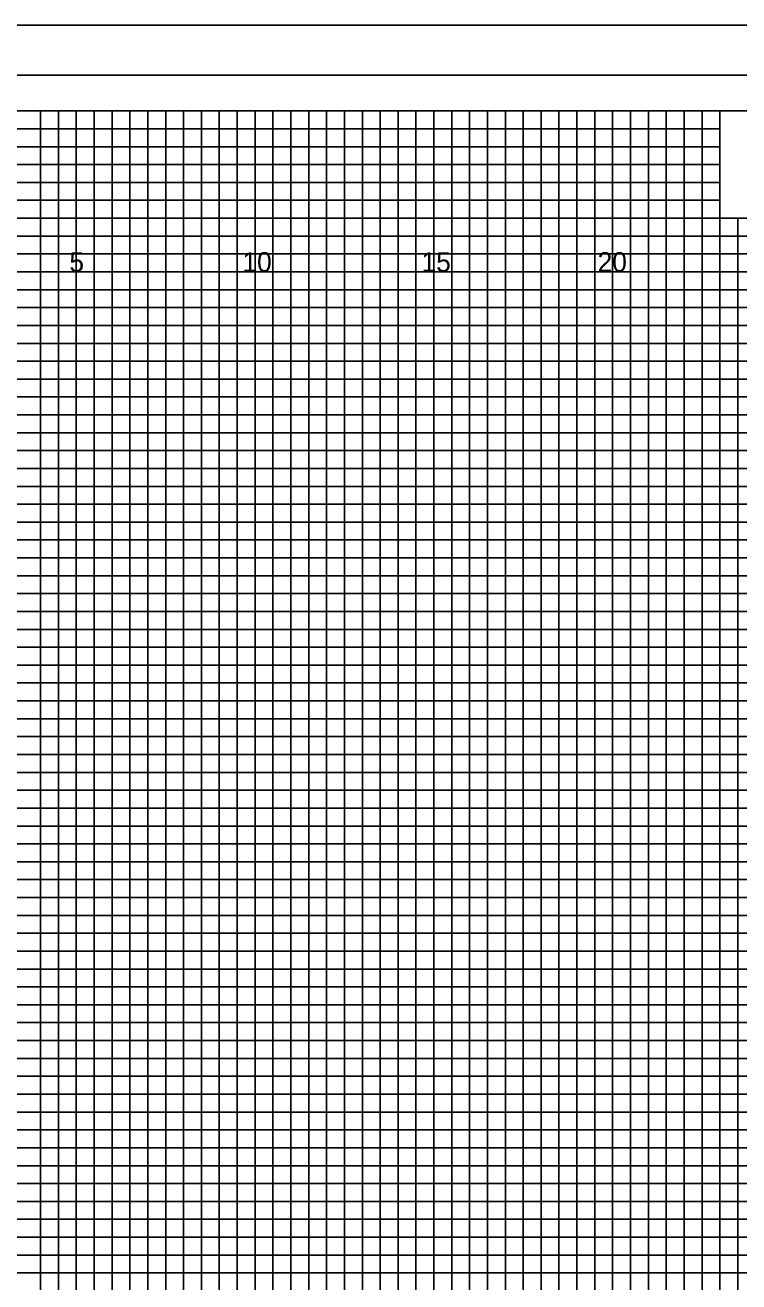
# Model space of a CAD drawing. Extents: x -4 to 103, y -2 to 67.
# Drawn here: x 54.82 to 74.78, y 32.25 to 67.4 of the extents above; entities that cross this region are included whole.
import ezdxf

# ---------------------------------------------------------------- set-up
doc = ezdxf.new("R2010")
doc.units = 0
for name, color, linetype in [('Old_Level_10', 7, 'Continuous'), ('Old_Level_16', 7, 'Continuous'), ('Old_Level_3', 7, 'Continuous'), ('Old_Level_4', 7, 'Continuous'), ('Old_Level_5', 7, 'Continuous'), ('Old_Level_6', 7, 'Continuous'), ('Old_Level_8', 7, 'Continuous'), ('Prop XSC Text', 7, 'Continuous')]:
    doc.layers.add(name, color=color, linetype=linetype)

msp = doc.modelspace()

# ---------------------------------------------------------------- linework, layer by layer
at = {"layer": 'Old_Level_10'}
for p, q in [((56.25, 0), (56.25, 65)), ((58.75, 0), (58.75, 65)), ((61.25, 0), (61.25, 65)), ((63.75, 0), (63.75, 65)), ((66.25, 0), (66.25, 65)), ((68.75, 0), (68.75, 65)), ((71.25, 0), (71.25, 65)), ((73.75, 0), (73.75, 65)), ((0, 62.5), (74.25, 62.5)), ((0, 60), (102.5, 60)), ((0, 57.5), (102.5, 57.5)), ((0, 55), (102.5, 55)), ((0, 52.5), (102.5, 52.5)), ((0, 50), (102.5, 50)), ((0, 47.5), (102.5, 47.5)), ((0, 45), (102.5, 45)), ((0, 42.5), (102.5, 42.5)), ((0, 40), (102.5, 40)), ((0, 37.5), (102.5, 37.5)), ((0, 35), (102.5, 35)), ((0, 32.5), (102.5, 32.5))]:
    msp.add_line(p, q, dxfattribs=at)
at = {"layer": 'Old_Level_3'}
msp.add_line((-3.5, 67.4), (103.4, 67.4), dxfattribs=at)
at = {"layer": 'Old_Level_4'}
msp.add_lwpolyline([(103, 66), (-2.8, 66), (-2.8, -1), (103, -1)], close=True, dxfattribs=at)
at = {"layer": 'Old_Level_5'}
msp.add_lwpolyline([(103.4, 67.4), (-3.5, 67.4), (-3.5, -2.425), (103.4, -2.425)], close=True, dxfattribs=at)
at = {"layer": 'Old_Level_6'}
for points in [[(102.5, 65), (0, 65), (0, 0), (102.5, 0)], [(83.75, 65), (74.25, 65), (74.25, 62), (83.75, 62)]]:
    msp.add_lwpolyline(points, close=True, dxfattribs=at)
at = {"layer": 'Old_Level_8'}
for points in [[(56.25, 0), (56.25, 65), (58.75, 65), (58.75, 0)], [(61.25, 0), (61.25, 65), (63.75, 65), (63.75, 0)], [(66.25, 0), (66.25, 65), (68.75, 65), (68.75, 0)], [(71.25, 0), (71.25, 65), (73.75, 65), (73.75, 0)], [(0, 62.5), (74.25, 62.5)], [(0, 57.5), (102.5, 57.5), (102.5, 60), (0, 60)], [(0, 52.5), (102.5, 52.5), (102.5, 55), (0, 55)], [(0, 47.5), (102.5, 47.5), (102.5, 50), (0, 50)], [(0, 42.5), (102.5, 42.5), (102.5, 45), (0, 45)], [(0, 37.5), (102.5, 37.5), (102.5, 40), (0, 40)], [(0, 32.5), (102.5, 32.5), (102.5, 35), (0, 35)]]:
    msp.add_lwpolyline(points, dxfattribs=at)
at = {"layer": 'Prop XSC Text'}
for points in [[(55.25, 0), (55.25, 65), (55.75, 65), (55.75, 0)], [(56.75, 0), (56.75, 65), (57.25, 65), (57.25, 0)], [(57.75, 0), (57.75, 65), (58.25, 65), (58.25, 0)], [(59.25, 0), (59.25, 65), (59.75, 65), (59.75, 0)], [(60.25, 0), (60.25, 65), (60.75, 65), (60.75, 0)], [(61.75, 0), (61.75, 65), (62.25, 65), (62.25, 0)], [(62.75, 0), (62.75, 65), (63.25, 65), (63.25, 0)], [(64.25, 0), (64.25, 65), (64.75, 65), (64.75, 0)], [(65.25, 0), (65.25, 65), (65.75, 65), (65.75, 0)], [(66.75, 0), (66.75, 65), (67.25, 65), (67.25, 0)], [(67.75, 0), (67.75, 65), (68.25, 65), (68.25, 0)], [(69.25, 0), (69.25, 65)], [(69.25, 65), (69.75, 65), (69.75, 0)], [(70.25, 0), (70.25, 65), (70.75, 65), (70.75, 0)], [(71.75, 0), (71.75, 65), (72.25, 65), (72.25, 0)], [(72.75, 0), (72.75, 65), (73.25, 65), (73.25, 0)], [(0, 62), (0, 63), (74.25, 63), (74.25, 63.5), (0, 63.5), (0, 64), (74.25, 64), (74.25, 64.5), (0, 64.5)], [(0, 61.5), (102.5, 61.5), (102.5, 62), (0, 62)], [(74.25, 0), (74.25, 62), (74.75, 62), (74.75, 0)], [(0, 60.5), (102.5, 60.5), (102.5, 61), (0, 61)], [(0, 59), (102.5, 59), (102.5, 59.5), (0, 59.5)], [(0, 58), (102.5, 58), (102.5, 58.5), (0, 58.5)], [(0, 56.5), (102.5, 56.5), (102.5, 57), (0, 57)], [(0, 55.5), (102.5, 55.5), (102.5, 56), (0, 56)], [(0, 54), (102.5, 54), (102.5, 54.5), (0, 54.5)], [(0, 53), (102.5, 53), (102.5, 53.5), (0, 53.5)], [(0, 51.5), (102.5, 51.5), (102.5, 52), (0, 52)], [(0, 50.5), (102.5, 50.5), (102.5, 51), (0, 51)], [(0, 49), (102.5, 49), (102.5, 49.5), (0, 49.5)], [(0, 48), (102.5, 48), (102.5, 48.5), (0, 48.5)], [(0, 46.5), (102.5, 46.5), (102.5, 47), (0, 47)], [(0, 45.5), (102.5, 45.5), (102.5, 46), (0, 46)], [(0, 44), (102.5, 44), (102.5, 44.5), (0, 44.5)], [(0, 43), (102.5, 43), (102.5, 43.5), (0, 43.5)], [(0, 41.5), (102.5, 41.5), (102.5, 42), (0, 42)], [(0, 40.5), (102.5, 40.5), (102.5, 41), (0, 41)], [(0, 39), (102.5, 39), (102.5, 39.5), (0, 39.5)], [(0, 38), (102.5, 38), (102.5, 38.5), (0, 38.5)], [(0, 36.5), (102.5, 36.5), (102.5, 37), (0, 37)], [(0, 35.5), (102.5, 35.5), (102.5, 36), (0, 36)], [(0, 34), (102.5, 34), (102.5, 34.5), (0, 34.5)], [(0, 33), (102.5, 33), (102.5, 33.5), (0, 33.5)]]:
    msp.add_lwpolyline(points, dxfattribs=at)

# ---------------------------------------------------------------- texts
at = {"layer": 'Old_Level_16'}
for s, p in [('5', (56.057, 60.5)), ('10', (60.897, 60.5)), ('15', (65.906, 60.5)), ('20', (70.831, 60.5))]:
    msp.add_text(s, height=0.55, dxfattribs=at).set_placement(p)

doc.saveas('drawing.dxf')
